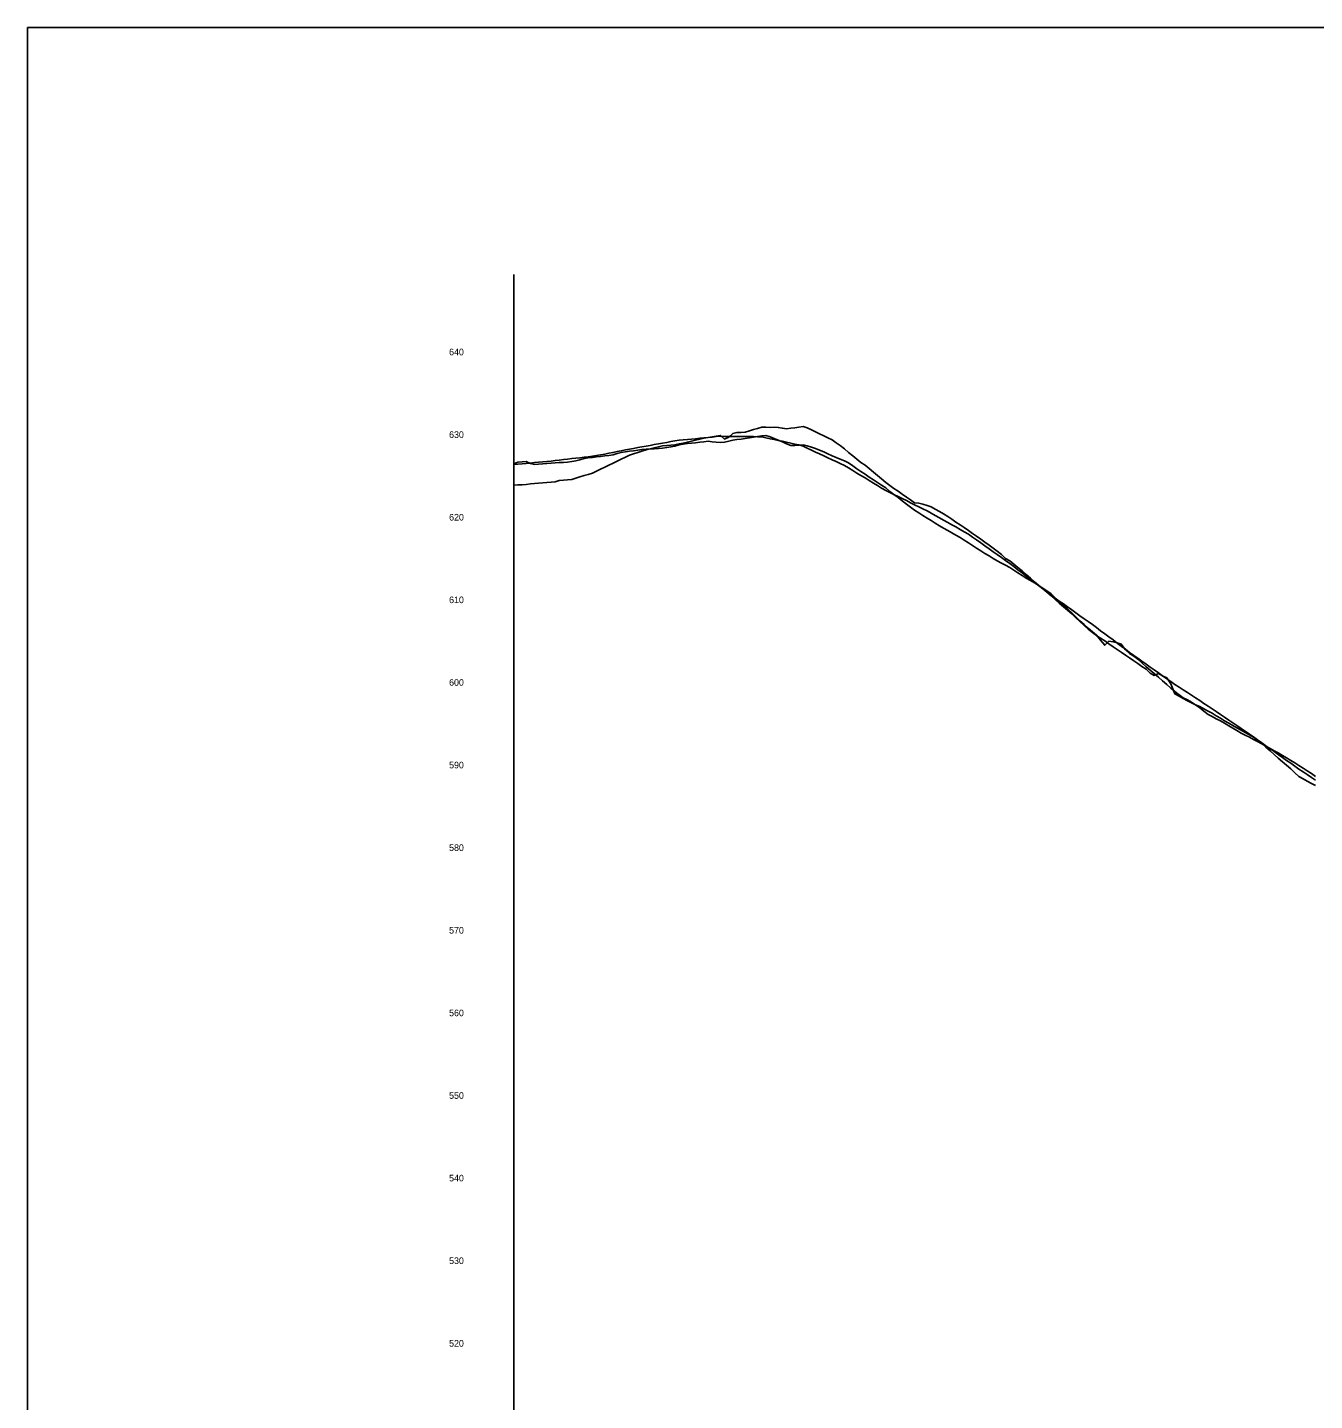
# Model space of a CAD drawing. Extents: x 1511486 to 1516886, y 901686 to 906985.
# Drawn here: x 1511486 to 1513044, y 905323 to 906985 of the extents above; entities that cross this region are included whole.
import ezdxf

# ---------------------------------------------------------------- set-up
doc = ezdxf.new("R2010")
doc.units = 0
for name, color, linetype in [('RD_DDB_ElevTX', 7, 'Continuous'), ('RD_DDB_Profile_EX', 7, 'Continuous'), ('RD_GPK_Profile_Cell', 7, 'Continuous'), ('RD_Sketch2', 7, 'Continuous'), ('RD_Sketch3', 7, 'Continuous')]:
    doc.layers.add(name, color=color, linetype=linetype)

msp = doc.modelspace()

# ---------------------------------------------------------------- linework, layer by layer
at = {"layer": 'RD_DDB_Profile_EX'}
for points in [[(1512074.7, 906456.1), (1512079.7, 906456.6), (1512084.7, 906457.1), (1512089.7, 906457.6), (1512094.7, 906458), (1512099.7, 906458.5), (1512104.7, 906459), (1512109.7, 906459.4), (1512114.7, 906459.9), (1512119.7, 906460.4), (1512124.7, 906460.9), (1512129.7, 906461.5), (1512134.7, 906462.1), (1512139.7, 906462.7), (1512144.7, 906463.3), (1512149.7, 906463.9), (1512154.7, 906464.5), (1512159.7, 906465.1), (1512164.7, 906465.7), (1512169.7, 906466.3), (1512174.7, 906467), (1512179.7, 906468), (1512184.7, 906468.9), (1512189.7, 906469.9), (1512194.7, 906470.9), (1512199.7, 906471.8), (1512204.7, 906472.8), (1512209.7, 906473.8), (1512214.7, 906474.8), (1512219.7, 906475.8), (1512224.7, 906476.7), (1512229.7, 906477.6), (1512234.7, 906478.5), (1512239.7, 906479.4), (1512244.7, 906480.3), (1512249.7, 906481.2), (1512254.7, 906482.1), (1512259.7, 906483), (1512264.7, 906483.9), (1512269.7, 906484.8), (1512274.7, 906485.6), (1512279.7, 906486), (1512284.7, 906486.5), (1512289.7, 906487), (1512294.7, 906487.5), (1512299.7, 906488), (1512304.7, 906488.5), (1512309.7, 906489), (1512314.7, 906489.4), (1512319.7, 906490), (1512324.7, 906490.4), (1512329.7, 906490.3), (1512334.7, 906490.2), (1512339.7, 906490.1), (1512344.7, 906490.3), (1512349.7, 906490.3), (1512354.7, 906490.2), (1512359.7, 906490.1), (1512364.7, 906490), (1512369.7, 906489.9), (1512374.7, 906489.6), (1512379.7, 906488.5), (1512384.7, 906487.4), (1512389.7, 906486.4), (1512394.7, 906485.4), (1512399.7, 906484.3), (1512404.7, 906483.2), (1512409.7, 906482.1), (1512414.7, 906481), (1512419.7, 906479.9), (1512424.7, 906478.3), (1512429.7, 906476), (1512434.7, 906473.7), (1512439.7, 906471.3), (1512444.7, 906469), (1512449.7, 906466.7), (1512454.7, 906464.4), (1512459.7, 906462), (1512464.7, 906459.7), (1512469.7, 906457.4), (1512474.7, 906455), (1512479.7, 906452), (1512484.7, 906449), (1512489.7, 906445.9), (1512494.7, 906442.9), (1512499.7, 906439.9), (1512504.7, 906436.9), (1512509.7, 906433.8), (1512514.7, 906430.8), (1512519.7, 906427.7), (1512524.7, 906424.7), (1512529.7, 906422.3), (1512534.7, 906419.9), (1512539.7, 906417.4), (1512544.7, 906415), (1512549.7, 906412.5), (1512554.7, 906410), (1512559.7, 906407.6), (1512564.7, 906405.1), (1512569.7, 906402.6), (1512574.7, 906400.1)], [(1512574.7, 906400.1), (1512579.7, 906397.3), (1512584.7, 906394.6), (1512589.7, 906391.8), (1512594.7, 906389), (1512599.7, 906386.2), (1512604.7, 906383.4), (1512609.7, 906380.6), (1512614.7, 906377.7), (1512619.7, 906374.8), (1512624.7, 906371.8), (1512629.7, 906368.3), (1512634.7, 906364.9), (1512639.7, 906361.4), (1512644.7, 906357.8), (1512649.7, 906354.3), (1512654.7, 906350.7), (1512659.7, 906347.1), (1512664.7, 906343.5), (1512669.7, 906340), (1512674.7, 906336.4), (1512679.7, 906332.6), (1512684.7, 906328.7), (1512689.7, 906324.9), (1512694.7, 906321.1), (1512699.7, 906317.3), (1512704.7, 906313.5), (1512709.7, 906309.6), (1512714.7, 906305.8), (1512719.7, 906301.9), (1512724.7, 906298.1), (1512729.7, 906294.5), (1512734.7, 906291), (1512739.7, 906287.4), (1512744.7, 906283.8), (1512749.7, 906280.2), (1512754.7, 906276.7), (1512759.7, 906273.1), (1512764.7, 906269.6), (1512769.7, 906266.1), (1512774.7, 906262.5), (1512779.7, 906258.8), (1512784.7, 906255), (1512789.7, 906251.3), (1512794.7, 906247.6), (1512799.7, 906243.8), (1512804.7, 906240.1), (1512809.7, 906236.3), (1512814.7, 906232.5), (1512819.7, 906228.8), (1512824.7, 906225.1), (1512829.7, 906221.6), (1512834.7, 906218.1), (1512839.7, 906214.5), (1512844.7, 906211), (1512849.7, 906207.5), (1512854.7, 906204), (1512859.7, 906200.4), (1512864.7, 906196.9), (1512869.7, 906193.4), (1512874.7, 906189.9), (1512879.7, 906186.7), (1512884.7, 906183.5), (1512889.7, 906180.2), (1512894.7, 906177), (1512899.7, 906173.7), (1512904.7, 906170.4), (1512909.7, 906167.1), (1512914.7, 906163.8), (1512919.7, 906160.5), (1512924.7, 906157.2), (1512929.7, 906153.8), (1512934.7, 906150.4), (1512939.7, 906146.9), (1512944.7, 906143.5), (1512949.7, 906140.1), (1512954.7, 906136.7), (1512959.7, 906133.3), (1512964.7, 906129.9), (1512969.7, 906126.4), (1512974.7, 906122.9), (1512979.7, 906119.4), (1512984.7, 906115.8), (1512989.7, 906112.2), (1512994.7, 906108.7), (1512999.7, 906105.1), (1513004.7, 906101.6), (1513009.7, 906098), (1513014.7, 906094.5), (1513019.7, 906090.9), (1513024.7, 906087.4), (1513029.7, 906084.1), (1513034.7, 906080.8), (1513039.7, 906077.5), (1513044.7, 906074.2)]]:
    msp.add_lwpolyline(points, dxfattribs=at)
at = {"layer": 'RD_GPK_Profile_Cell'}
msp.add_line((1512074.7, 904186.4), (1512074.7, 906686.4), dxfattribs=at)
at = {"layer": 'RD_Sketch2'}
for points in [[(1512074.7, 906431.2), (1512079.7, 906431.5), (1512084.7, 906431.8), (1512089.7, 906432.2), (1512094.7, 906432.7), (1512099.7, 906433.2), (1512104.7, 906433.6), (1512109.7, 906434), (1512114.7, 906434.4), (1512119.7, 906434.8), (1512124.7, 906435.3), (1512129.7, 906436.8), (1512134.7, 906437.2), (1512139.7, 906437.5), (1512144.7, 906438.2), (1512149.7, 906439.7), (1512154.7, 906441.3), (1512159.7, 906442.8), (1512164.7, 906444.3), (1512169.7, 906445.8), (1512174.7, 906448.1), (1512179.7, 906450.4), (1512184.7, 906452.9), (1512189.7, 906455.5), (1512194.7, 906457.9), (1512199.7, 906460.2), (1512204.7, 906462.6), (1512209.7, 906465), (1512214.7, 906467.4), (1512219.7, 906469.2), (1512224.7, 906470.9), (1512229.7, 906472.5), (1512234.7, 906474), (1512239.7, 906475.2), (1512244.7, 906476.4), (1512249.7, 906477.5), (1512254.7, 906478.7), (1512259.7, 906479.2), (1512264.7, 906479.6), (1512269.7, 906480.1), (1512274.7, 906481.1), (1512279.7, 906482.2), (1512284.7, 906483.4), (1512289.7, 906484.5), (1512294.7, 906485.7), (1512299.7, 906487), (1512304.7, 906488.3), (1512309.7, 906489), (1512314.7, 906489.7), (1512319.7, 906490.4), (1512324.7, 906491.5), (1512329.7, 906486.9), (1512334.7, 906489.2), (1512339.7, 906493.9), (1512344.7, 906494.8), (1512349.7, 906494.9), (1512354.7, 906495.5), (1512359.7, 906497), (1512364.7, 906498.5), (1512369.7, 906500), (1512374.7, 906501.5), (1512379.7, 906501.3), (1512384.7, 906500.9), (1512389.7, 906501.3), (1512394.7, 906501.1), (1512399.7, 906500.2), (1512404.7, 906499.5), (1512409.7, 906500.2), (1512414.7, 906500.8), (1512419.7, 906501.5), (1512424.7, 906502.1), (1512429.7, 906500.5), (1512434.7, 906498.1), (1512439.7, 906495.8), (1512444.7, 906493.4), (1512449.7, 906491.1), (1512454.7, 906488.7), (1512459.7, 906486), (1512464.7, 906482.5), (1512469.7, 906479.1), (1512474.7, 906475.1), (1512479.7, 906470.9), (1512484.7, 906466.8), (1512489.7, 906462.6), (1512494.7, 906458.8), (1512499.7, 906455.3), (1512504.7, 906451.2), (1512509.7, 906447.1), (1512514.7, 906443), (1512519.7, 906438.8), (1512524.7, 906434.6), (1512529.7, 906430.8), (1512534.7, 906427.3), (1512539.7, 906423.8), (1512544.7, 906420.3), (1512549.7, 906416.8), (1512554.7, 906413.3), (1512559.7, 906409.7), (1512564.7, 906409.6), (1512569.7, 906408.2), (1512574.7, 906406.7)], [(1512075.5, 906457.4), (1512079.7, 906459), (1512084.7, 906459.3), (1512089.7, 906459.7), (1512094.7, 906457.6), (1512099.7, 906456.4), (1512104.7, 906456.8), (1512109.7, 906457.2), (1512114.7, 906457.6), (1512119.7, 906457.9), (1512124.7, 906458.2), (1512129.7, 906458.5), (1512134.7, 906458.7), (1512139.7, 906459.1), (1512144.7, 906459.9), (1512149.7, 906460.6), (1512154.7, 906461.9), (1512159.7, 906463.6), (1512164.7, 906464.2), (1512169.7, 906464.8), (1512174.7, 906465.4), (1512179.7, 906466.1), (1512184.7, 906466.6), (1512189.7, 906467.2), (1512194.7, 906468.1), (1512199.7, 906469.5), (1512204.7, 906470.8), (1512209.7, 906471.5), (1512214.7, 906472.3), (1512219.7, 906472.9), (1512224.7, 906473.6), (1512229.7, 906474.2), (1512234.7, 906474.9), (1512239.7, 906475.1), (1512244.7, 906475.1), (1512249.7, 906475.5), (1512254.7, 906476.2), (1512259.7, 906476.8), (1512264.7, 906477.5), (1512269.7, 906478.6), (1512274.7, 906479.9), (1512279.7, 906481), (1512284.7, 906481.5), (1512289.7, 906482.1), (1512294.7, 906482.6), (1512299.7, 906483.2), (1512304.7, 906483.8), (1512309.7, 906484.3), (1512314.7, 906483.8), (1512319.7, 906483.3), (1512324.7, 906482.8), (1512329.7, 906483.4), (1512334.7, 906484.6), (1512339.7, 906485.8), (1512344.7, 906486.4), (1512349.7, 906486.9), (1512354.7, 906487.7), (1512359.7, 906488.5), (1512364.7, 906489.3), (1512369.7, 906490), (1512374.7, 906490.8), (1512379.7, 906491.5), (1512384.7, 906489.6), (1512389.7, 906487.7), (1512394.7, 906485.7), (1512399.7, 906483.6), (1512404.7, 906481.3), (1512409.7, 906479.1), (1512414.7, 906479.4), (1512419.7, 906479.7), (1512424.7, 906480.1), (1512429.7, 906479), (1512434.7, 906477.4), (1512439.7, 906475.5), (1512444.7, 906473.7), (1512449.7, 906471.5), (1512454.7, 906469), (1512459.7, 906466.8), (1512464.7, 906464.7), (1512469.7, 906462.7), (1512474.7, 906460.8), (1512479.7, 906458.1), (1512484.7, 906454.6), (1512489.7, 906451.1), (1512494.7, 906447.7), (1512499.7, 906444.4), (1512504.7, 906441), (1512509.7, 906437.7), (1512514.7, 906434.4), (1512519.7, 906431.1), (1512524.7, 906427.8), (1512529.7, 906423.7), (1512534.7, 906420.1), (1512539.7, 906416.4), (1512544.7, 906412.3), (1512549.7, 906408.2), (1512554.7, 906404.5), (1512559.7, 906401.1), (1512564.7, 906397.7), (1512569.7, 906394.4), (1512574.7, 906391.3)], [(1512574.7, 906406.7), (1512579.7, 906405.1), (1512584.7, 906402.3), (1512589.7, 906399.2), (1512594.7, 906396.6), (1512599.7, 906393.3), (1512604.7, 906390), (1512609.7, 906386.6), (1512614.7, 906383.3), (1512619.7, 906379.9), (1512624.7, 906376.4), (1512629.7, 906372.9), (1512634.7, 906369.4), (1512639.7, 906365.8), (1512644.7, 906362.2), (1512649.7, 906358.5), (1512654.7, 906354.9), (1512659.7, 906351.2), (1512664.7, 906347.2), (1512669.7, 906342.6), (1512674.7, 906339.6), (1512679.7, 906335.6), (1512684.7, 906331.6), (1512689.7, 906327.5), (1512694.7, 906323), (1512699.7, 906318.7), (1512704.7, 906314.4), (1512709.7, 906310.1), (1512714.7, 906305.9), (1512719.7, 906301.6), (1512724.7, 906297.3), (1512729.7, 906292.9), (1512734.7, 906288.5), (1512739.7, 906284.1), (1512744.7, 906279.9), (1512749.7, 906275.3), (1512754.7, 906270.7), (1512759.7, 906266.1), (1512764.7, 906261.5), (1512769.7, 906256.9), (1512774.7, 906252.7), (1512779.7, 906249.4), (1512784.7, 906246), (1512789.7, 906242.7), (1512794.7, 906239), (1512799.7, 906235.6), (1512804.7, 906232.3), (1512809.7, 906228.9), (1512814.7, 906225.6), (1512819.7, 906222.3), (1512824.7, 906218.6), (1512829.7, 906215.3), (1512834.7, 906211.8), (1512839.7, 906208.3), (1512844.7, 906203.7), (1512849.7, 906201), (1512854.7, 906203.1), (1512859.7, 906200.5), (1512864.7, 906198), (1512869.7, 906190.8), (1512874.7, 906178.5), (1512879.7, 906176), (1512884.7, 906173.1), (1512889.7, 906170.1), (1512894.7, 906167.8), (1512899.7, 906165.5), (1512904.7, 906163.2), (1512909.7, 906160.5), (1512914.7, 906157.8), (1512919.7, 906155.1), (1512924.7, 906151.8), (1512929.7, 906149), (1512934.7, 906146.1), (1512939.7, 906143.2), (1512944.7, 906140.4), (1512949.7, 906137.5), (1512954.7, 906134.7), (1512959.7, 906131.8), (1512964.7, 906129), (1512969.7, 906126.1), (1512974.7, 906122.7), (1512979.7, 906118.4), (1512984.7, 906114), (1512989.7, 906109.7), (1512994.7, 906105.2), (1512999.7, 906100.8), (1513004.7, 906096.5), (1513009.7, 906092.1), (1513014.7, 906087.7), (1513019.7, 906083.2), (1513024.7, 906078.6), (1513029.7, 906075.6), (1513034.7, 906072.8), (1513039.7, 906070.2), (1513044.7, 906067.7)], [(1512574.7, 906391.3), (1512579.7, 906388.4), (1512584.7, 906385.1), (1512589.7, 906381.9), (1512594.7, 906379), (1512599.7, 906376.2), (1512604.7, 906373.5), (1512609.7, 906370.8), (1512614.7, 906367.8), (1512619.7, 906364.7), (1512624.7, 906361.6), (1512629.7, 906358.1), (1512634.7, 906354.8), (1512639.7, 906351.9), (1512644.7, 906348.7), (1512649.7, 906345.5), (1512654.7, 906342.4), (1512659.7, 906339.7), (1512664.7, 906336.9), (1512669.7, 906334.2), (1512674.7, 906331.5), (1512679.7, 906328.3), (1512684.7, 906325.1), (1512689.7, 906321.9), (1512694.7, 906318.8), (1512699.7, 906315.8), (1512704.7, 906312.8), (1512709.7, 906309.7), (1512714.7, 906306.5), (1512719.7, 906303.4), (1512724.7, 906299.7), (1512729.7, 906295), (1512734.7, 906290.5), (1512739.7, 906286), (1512744.7, 906281.4), (1512749.7, 906276.6), (1512754.7, 906271.9), (1512759.7, 906267.1), (1512764.7, 906262.6), (1512769.7, 906258.1), (1512774.7, 906253.6), (1512779.7, 906249.6), (1512784.7, 906243.5), (1512789.7, 906237.5), (1512794.7, 906242.3), (1512799.7, 906241.4), (1512804.7, 906240.3), (1512809.7, 906238.8), (1512814.7, 906231.7), (1512819.7, 906227.6), (1512824.7, 906224.1), (1512829.7, 906220.7), (1512834.7, 906216.3), (1512839.7, 906211.5), (1512844.7, 906207.2), (1512849.7, 906203.3), (1512854.7, 906198.9), (1512859.7, 906194.4), (1512864.7, 906190), (1512869.7, 906185.6), (1512874.7, 906181.3), (1512879.7, 906177.5), (1512884.7, 906173.9), (1512889.7, 906171.2), (1512894.7, 906168.5), (1512899.7, 906165.4), (1512904.7, 906161.5), (1512909.7, 906157.7), (1512914.7, 906153.8), (1512919.7, 906151), (1512924.7, 906148.4), (1512929.7, 906145.8), (1512934.7, 906143), (1512939.7, 906140), (1512944.7, 906137), (1512949.7, 906134.1), (1512954.7, 906131.1), (1512959.7, 906128.4), (1512964.7, 906126), (1512969.7, 906123.5), (1512974.7, 906120.9), (1512979.7, 906118.3), (1512984.7, 906115.4), (1512989.7, 906112.4), (1512994.7, 906109.7), (1512999.7, 906107.1), (1513004.7, 906104.1), (1513009.7, 906101.1), (1513014.7, 906098.1), (1513019.7, 906095.1), (1513024.7, 906092), (1513029.7, 906088.7), (1513034.7, 906085.4), (1513039.7, 906082.1), (1513044.7, 906078.6)]]:
    msp.add_lwpolyline(points, dxfattribs=at)
at = {"layer": 'RD_Sketch3'}
msp.add_lwpolyline([(1511486.2, 906985.3), (1516886.2, 906985.3), (1516886.2, 903685.3), (1511486.2, 903685.3)], close=True, dxfattribs=at)

# ---------------------------------------------------------------- texts
at = {"layer": 'RD_DDB_ElevTX'}
for s, p in [('640', (1511996.4, 906588.4)), ('630', (1511996.4, 906488.4)), ('620', (1511996.4, 906388.4)), ('610', (1511996.4, 906288.4)), ('600', (1511996.4, 906188.4)), ('590', (1511996.4, 906088.4)), ('580', (1511996.4, 905988.4)), ('570', (1511996.4, 905888.4)), ('560', (1511996.4, 905788.4)), ('550', (1511996.4, 905688.4)), ('540', (1511996.4, 905588.4)), ('530', (1511996.4, 905488.4)), ('520', (1511996.4, 905388.4))]:
    msp.add_text(s, height=8, dxfattribs=at).set_placement(p)

doc.saveas('drawing.dxf')
